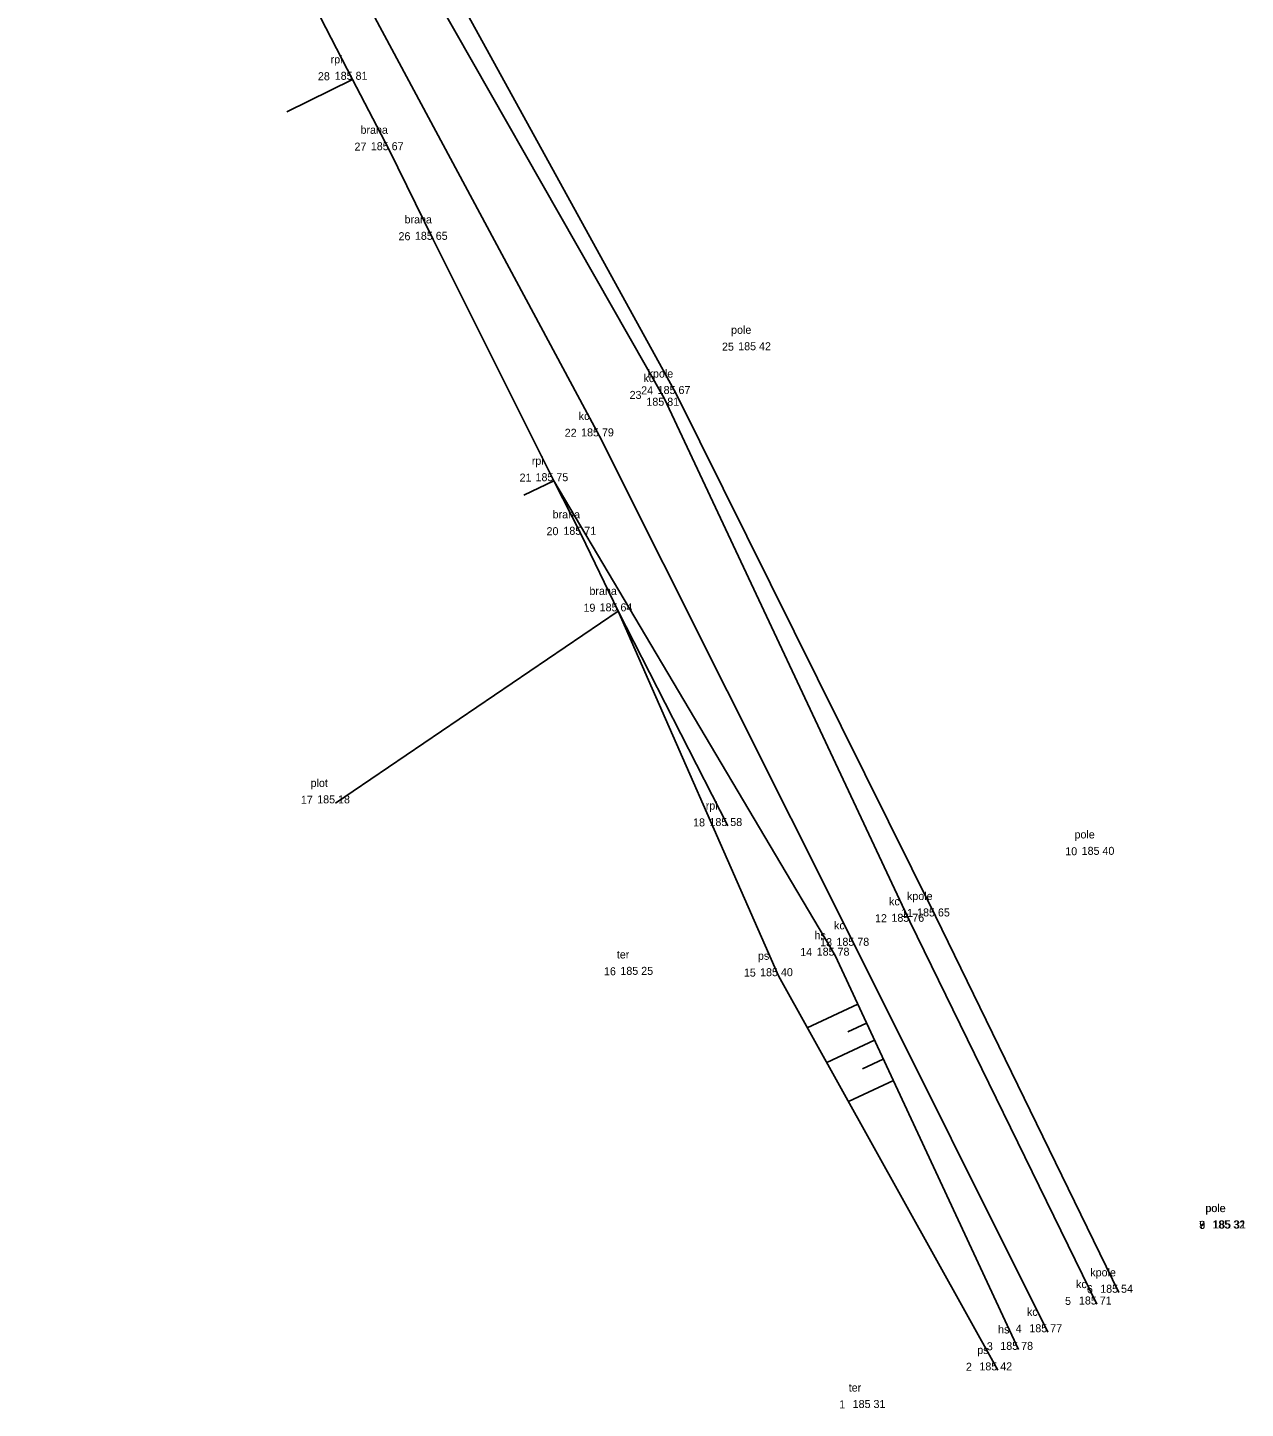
# Model space of a CAD drawing. Extents: x -598527 to -598215, y -1172822 to -1172560.
# Drawn here: x -598512.5 to -598466.8, y -1172822.4 to -1172770.6 of the extents above; entities that cross this region are included whole.
import ezdxf

# ---------------------------------------------------------------- set-up
doc = ezdxf.new("R2010")
doc.units = 0
for name, color, linetype in [('Body', 7, 'Continuous'), ('Body čísla', 7, 'Continuous'), ('Kody', 7, 'Continuous'), ('Kraj pole', 7, 'Continuous'), ('PATTERN_CLASS', 7, 'Continuous'), ('Ploty', 7, 'Continuous'), ('Výšky', 7, 'Continuous')]:
    doc.layers.add(name, color=color, linetype=linetype)

msp = doc.modelspace()

# ---------------------------------------------------------------- linework, layer by layer
at = {"layer": 'Body'}
for p, q in [((-598500.28, -1172772.53), (-598500.28, -1172772.53)), ((-598498.91, -1172775.17), (-598498.91, -1172775.17)), ((-598497.26, -1172778.53), (-598497.26, -1172778.53)), ((-598485.14, -1172782.67), (-598485.14, -1172782.67)), ((-598488.16, -1172784.31), (-598488.16, -1172784.31)), ((-598488.6, -1172784.48), (-598488.6, -1172784.48)), ((-598491.03, -1172785.9), (-598491.03, -1172785.9)), ((-598492.74, -1172787.58), (-598492.74, -1172787.58)), ((-598491.71, -1172789.59), (-598491.71, -1172789.59)), ((-598490.33, -1172792.46), (-598490.33, -1172792.46)), ((-598500.92, -1172799.66), (-598500.92, -1172799.66)), ((-598486.22, -1172800.51), (-598486.22, -1172800.51)), ((-598472.27, -1172801.59), (-598472.27, -1172801.59)), ((-598478.44, -1172803.9), (-598478.44, -1172803.9)), ((-598479.4, -1172804.1), (-598479.4, -1172804.1)), ((-598481.46, -1172805), (-598481.46, -1172805)), ((-598482.2, -1172805.37), (-598482.2, -1172805.37)), ((-598489.56, -1172806.09), (-598489.56, -1172806.09)), ((-598484.32, -1172806.14), (-598484.32, -1172806.14)), ((-598467.37, -1172815.6), (-598467.37, -1172815.6)), ((-598467.36, -1172815.6), (-598467.36, -1172815.6)), ((-598467.36, -1172815.6), (-598467.36, -1172815.6)), ((-598472.39, -1172818.45), (-598472.39, -1172818.45)), ((-598471.57, -1172818.01), (-598471.57, -1172818.01)), ((-598474.23, -1172819.49), (-598474.23, -1172819.49)), ((-598475.32, -1172820.15), (-598475.32, -1172820.15)), ((-598476.1, -1172820.92), (-598476.1, -1172820.92)), ((-598480.87, -1172822.33), (-598480.87, -1172822.33))]:
    msp.add_line(p, q, dxfattribs=at)
at = {"layer": 'Kraj pole'}
for p, q in [((-598498.97, -1172764.63), (-598488.16, -1172784.31)), ((-598488.16, -1172784.31), (-598478.44, -1172803.9)), ((-598478.44, -1172803.9), (-598471.57, -1172818.01))]:
    msp.add_line(p, q, dxfattribs=at)
at = {"layer": 'PATTERN_CLASS'}
for p, q in [((-598482.2, -1172805.37), (-598492.74, -1172787.58)), ((-598484.32, -1172806.14), (-598490.33, -1172792.46)), ((-598475.32, -1172820.15), (-598482.2, -1172805.37)), ((-598484.32, -1172806.14), (-598476.1, -1172820.92)), ((-598481.348, -1172807.201), (-598483.24, -1172808.082)), ((-598481.017, -1172807.911), (-598481.723, -1172808.24)), ((-598480.719, -1172808.551), (-598482.514, -1172809.387)), ((-598480.393, -1172809.253), (-598481.173, -1172809.616)), ((-598480.016, -1172810.062), (-598481.702, -1172810.847))]:
    msp.add_line(p, q, dxfattribs=at)
for points in [[(-598472.39, -1172818.45), (-598479.4, -1172804.1), (-598488.6, -1172784.48), (-598499.71, -1172764.97), (-598504.53, -1172755), (-598507.77, -1172746.6), (-598509.84, -1172736.8), (-598510.17, -1172728.48), (-598509.56, -1172717.51), (-598507.9, -1172705.69)], [(-598474.23, -1172819.49), (-598481.46, -1172805), (-598491.03, -1172785.9), (-598501.92, -1172765.58), (-598506.72, -1172756.28), (-598510.41, -1172747.04), (-598512.46, -1172737.25), (-598512.37, -1172728.07), (-598511.98, -1172717.34)]]:
    msp.add_lwpolyline(points, dxfattribs=at)
at = {"layer": 'Ploty'}
for p, q in [((-598500.28, -1172772.53), (-598503.23, -1172766.81)), ((-598500.28, -1172772.53), (-598502.746, -1172773.734)), ((-598498.91, -1172775.17), (-598500.28, -1172772.53)), ((-598497.26, -1172778.53), (-598498.91, -1172775.17)), ((-598492.74, -1172787.58), (-598497.26, -1172778.53)), ((-598492.74, -1172787.58), (-598493.859, -1172788.11)), ((-598491.71, -1172789.59), (-598492.74, -1172787.58)), ((-598490.33, -1172792.46), (-598491.71, -1172789.59)), ((-598490.33, -1172792.46), (-598500.92, -1172799.66)), ((-598486.22, -1172800.51), (-598490.33, -1172792.46))]:
    msp.add_line(p, q, dxfattribs=at)

# ---------------------------------------------------------------- texts
at = {"layer": 'Body čísla'}
for s, p in [('28', (-598501.581, -1172772.553)), ('27', (-598500.211, -1172775.193)), ('26', (-598498.56, -1172778.553)), ('25', (-598486.438, -1172782.693)), ('23', (-598489.9, -1172784.503)), ('24', (-598489.467, -1172784.333)), ('22', (-598492.333, -1172785.923)), ('21', (-598494.024, -1172787.603)), ('20', (-598493.013, -1172789.613)), ('19', (-598491.629, -1172792.483)), ('17', (-598502.221, -1172799.683)), ('18', (-598487.521, -1172800.533)), ('10', (-598473.573, -1172801.613)), ('12', (-598480.703, -1172804.123)), ('11', (-598479.724, -1172803.923)), ('13', (-598482.76, -1172805.023)), ('14', (-598483.507, -1172805.393)), ('16', (-598490.86, -1172806.113)), ('15', (-598485.618, -1172806.163)), ('7', (-598468.564, -1172815.623)), ('8', (-598468.553, -1172815.623)), ('9', (-598468.552, -1172815.623)), ('6', (-598472.763, -1172818.033)), ('5', (-598473.581, -1172818.473)), ('4', (-598475.43, -1172819.513)), ('3', (-598476.512, -1172820.173)), ('2', (-598477.296, -1172820.943)), ('1', (-598482.047, -1172822.353))]:
    msp.add_text(s, height=0.3, dxfattribs=at).set_placement(p)
at = {"layer": 'Kody'}
for s, p in [('rpl', (-598501.106, -1172771.923)), ('brana', (-598499.985, -1172774.563)), ('brana', (-598498.335, -1172777.923)), ('pole', (-598486.097, -1172782.063)), ('kc', (-598489.378, -1172783.873)), ('kpole', (-598489.224, -1172783.703)), ('kc', (-598491.808, -1172785.293)), ('rpl', (-598493.566, -1172786.973)), ('brana', (-598492.785, -1172788.983)), ('brana', (-598491.405, -1172791.853)), ('plot', (-598501.855, -1172799.053)), ('rpl', (-598487.046, -1172799.903)), ('pole', (-598473.227, -1172800.983)), ('kpole', (-598479.504, -1172803.293)), ('kc', (-598480.178, -1172803.493)), ('hs', (-598482.971, -1172804.763)), ('kc', (-598482.238, -1172804.393)), ('ter', (-598490.379, -1172805.483)), ('ps', (-598485.091, -1172805.533)), ('pole', (-598468.327, -1172814.993)), ('pole', (-598468.317, -1172814.993)), ('pole', (-598468.317, -1172814.993)), ('kpole', (-598472.634, -1172817.403)), ('kc', (-598473.168, -1172817.843)), ('kc', (-598475.008, -1172818.883)), ('hs', (-598476.091, -1172819.543)), ('ps', (-598476.871, -1172820.313)), ('ter', (-598481.689, -1172821.723))]:
    msp.add_text(s, height=0.3, dxfattribs=at).set_placement(p)
at = {"layer": 'Výšky'}
for s, p in [('185 81', (-598500.951, -1172772.538)), ('185 67', (-598499.599, -1172775.178)), ('185 65', (-598497.946, -1172778.538)), ('185 42', (-598485.831, -1172782.678)), ('185 67', (-598488.849, -1172784.318)), ('185 81', (-598489.271, -1172784.759)), ('185 79', (-598491.717, -1172785.908)), ('185 75', (-598493.426, -1172787.588)), ('185 71', (-598492.381, -1172789.598)), ('185 64', (-598491.024, -1172792.468)), ('185 18', (-598501.608, -1172799.668)), ('185 58', (-598486.908, -1172800.518)), ('185 40', (-598472.96, -1172801.598)), ('185 76', (-598480.088, -1172804.108)), ('185 65', (-598479.126, -1172803.908)), ('185 78', (-598482.148, -1172805.008)), ('185 78', (-598482.888, -1172805.378)), ('185 25', (-598490.246, -1172806.098)), ('185 40', (-598485.01, -1172806.148)), ('185 32', (-598468.061, -1172815.608)), ('185 31', (-598468.031, -1172815.608)), ('185 31', (-598468.031, -1172815.608)), ('185 54', (-598472.264, -1172818.018)), ('185 71', (-598473.061, -1172818.458)), ('185 77', (-598474.919, -1172819.498)), ('185 78', (-598476.008, -1172820.158)), ('185 42', (-598476.791, -1172820.928)), ('185 31', (-598481.541, -1172822.338))]:
    msp.add_text(s, height=0.3, dxfattribs=at).set_placement(p)

doc.saveas('drawing.dxf')
